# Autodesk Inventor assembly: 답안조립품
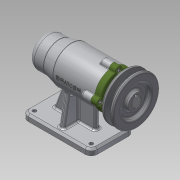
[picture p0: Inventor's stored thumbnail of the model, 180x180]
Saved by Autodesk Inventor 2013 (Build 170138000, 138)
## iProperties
Created: 2019-07
Part Number: 답안조립품
Document SubType Name: Assembly
Designer: Administrator
Author: Administrator
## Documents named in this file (12)
- C:\Users\Administrator\Desktop\490704V1034\답안조립품.iam
- C:\Users\Administrator\Desktop\490704V1034\본체.ipt
- C:\Users\Administrator\Desktop\490704V1034\V벨트풀리.ipt
- C:\Users\Administrator\Desktop\490704V1034\멈춤나사 M3.ipt
- C:\Users\Administrator\Desktop\490704V1034\베어링 6004.ipt
- C:\Users\Administrator\Desktop\490704V1034\베어링 51202.ipt
- C:\Users\Administrator\Desktop\490704V1034\볼트 M4.ipt
- C:\Users\Administrator\Desktop\490704V1034\어댑터슬리브.ipt
- C:\Users\Administrator\Desktop\490704V1034\오일 실.ipt
- C:\Users\Administrator\Desktop\490704V1034\축.ipt
- C:\Users\Administrator\Desktop\490704V1034\커버.ipt
- C:\Users\Administrator\Desktop\490704V1034\키 5 x 5 x 16.ipt
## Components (1 placed, 1 different names)
1. V벨트풀리:1
